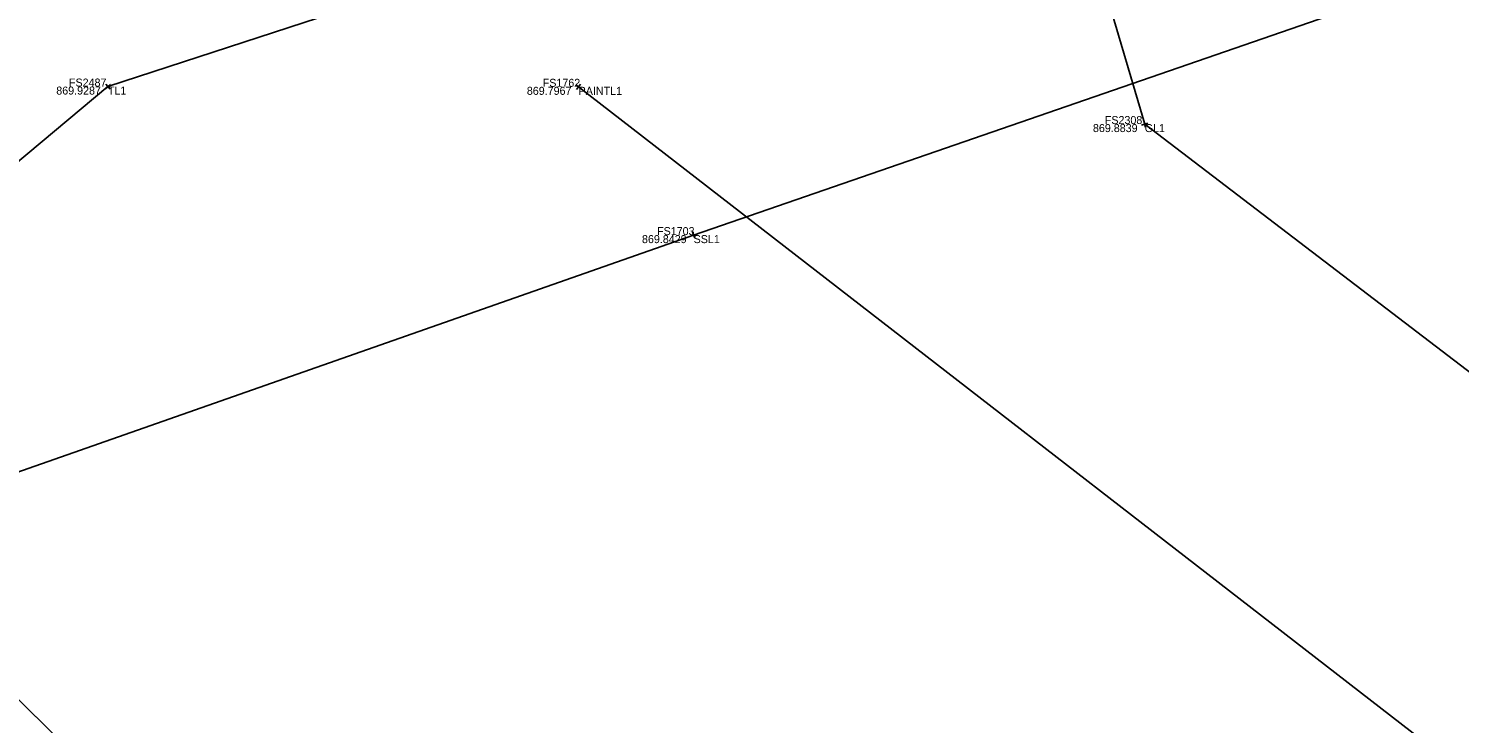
# Model space of a CAD drawing. Extents: x 1479425 to 1480294, y 379351 to 380102.
# Drawn here: x 1479659.17 to 1479669.9, y 379936.02 to 379941.22 of the extents above; entities that cross this region are included whole.
import ezdxf

# ---------------------------------------------------------------- set-up
doc = ezdxf.new("R2010")
doc.units = 0
for name, color, linetype in [('PM_X_Crosswalk', 7, 'Continuous'), ('SV_X_Shot_Marker', 7, 'Continuous'), ('SV_X_Text_Comment', 7, 'Continuous'), ('SV_X_Text_Elevation', 7, 'Continuous'), ('SV_X_Text_Name', 7, 'Continuous'), ('UT_X_Gas', 7, 'Continuous'), ('UT_X_Sanitary_Line', 7, 'Continuous'), ('UT_X_Telecom', 7, 'Continuous'), ('UT_X_Water', 7, 'Continuous')]:
    doc.layers.add(name, color=color, linetype=linetype)

msp = doc.modelspace()

# ---------------------------------------------------------------- linework, layer by layer
at = {"layer": 'PM_X_Crosswalk'}
msp.add_lwpolyline([(1479663.295, 379940.786), (1479694.651, 379916.513)], dxfattribs=at)
at = {"layer": 'SV_X_Shot_Marker'}
for p, q in [((1479659.748, 379940.772), (1479659.786, 379940.804)), ((1479659.751, 379940.807), (1479659.783, 379940.769)), ((1479659.767, 379940.788), (1479659.767, 379940.788)), ((1479663.275, 379940.801), (1479663.315, 379940.771)), ((1479663.31, 379940.806), (1479663.28, 379940.766)), ((1479663.295, 379940.786), (1479663.295, 379940.786)), ((1479667.562, 379940.514), (1479667.514, 379940.5)), ((1479667.531, 379940.531), (1479667.545, 379940.483)), ((1479667.538, 379940.507), (1479667.538, 379940.507)), ((1479664.133, 379939.667), (1479664.181, 379939.683)), ((1479664.149, 379939.699), (1479664.165, 379939.651)), ((1479664.157, 379939.675), (1479664.157, 379939.675))]:
    msp.add_line(p, q, dxfattribs=at)
at = {"layer": 'UT_X_Gas'}
msp.add_lwpolyline([(1479667.444, 379946.572), (1479666.862, 379942.802), (1479667.538, 379940.507), (1479675.403, 379934.504), (1479682.743, 379926.326), (1479692.421, 379916.824), (1479702.659, 379906.694), (1479713.881, 379895.567), (1479724.225, 379885.781), (1479733.117, 379877.795), (1479742.697, 379869.326), (1479754.816, 379857.131), (1479762.869, 379849.318), (1479772.436, 379840.641), (1479780.346, 379832.715), (1479784.901, 379828.191), (1479795.906, 379818.324), (1479806.128, 379806.719), (1479816.671, 379794.927)], dxfattribs=at)
at = {"layer": 'UT_X_Sanitary_Line'}
msp.add_lwpolyline([(1479514.622, 379866.87), (1479542.109, 379880.195), (1479565.169, 379891.725), (1479588.442, 379902.577), (1479600.276, 379909.045), (1479620.421, 379921.063), (1479621.963, 379921.485), (1479624.647, 379923.417), (1479645.234, 379932.512), (1479652.585, 379935.616), (1479664.157, 379939.675), (1479679.103, 379944.837), (1479710.112, 379956.448), (1479736.037, 379968.233), (1479798.147, 379991.168), (1479820.4, 379999.933), (1479823.042, 380000.22)], dxfattribs=at)
at = {"layer": 'UT_X_Telecom'}
msp.add_lwpolyline([(1479654.736, 379936.58), (1479659.767, 379940.788), (1479670.95, 379944.434), (1479693.183, 379956.652)], dxfattribs=at)
at = {"layer": 'UT_X_Water'}
msp.add_lwpolyline([(1479643.418, 379958.357), (1479650.478, 379950.403), (1479653.168, 379946.48), (1479654.757, 379940.471), (1479659.938, 379935.366), (1479675.346, 379920.322), (1479682.752, 379913.809), (1479688.353, 379908.314), (1479695.924, 379900.161), (1479705.441, 379891.596), (1479719.261, 379878.171), (1479726.79, 379870.913), (1479729.608, 379870.544), (1479735.551, 379869.684), (1479739.947, 379866.49), (1479744.65, 379861.847), (1479745.833, 379856.023), (1479753.929, 379847.124), (1479764.701, 379835.97), (1479779.815, 379822.167), (1479798.248, 379804.283), (1479815.468, 379787.444)], dxfattribs=at)

# ---------------------------------------------------------------- texts
at = {"layer": 'SV_X_Text_Comment'}
for s, p in [('TL1', (1479659.767, 379940.728)), ('PAINTL1', (1479663.295, 379940.726)), ('GL1', (1479667.538, 379940.447)), ('SSL1', (1479664.157, 379939.615))]:
    msp.add_text(s, height=0.06, dxfattribs=at).set_placement(p)
at = {"layer": 'SV_X_Text_Elevation'}
for s, p in [('869.9287', (1479659.38, 379940.728)), ('869.7967', (1479662.907, 379940.726)), ('869.8839', (1479667.15, 379940.447)), ('869.8429', (1479663.77, 379939.615))]:
    msp.add_text(s, height=0.06, dxfattribs=at).set_placement(p)
at = {"layer": 'SV_X_Text_Name'}
for s, p in [('FS2487', (1479659.475, 379940.788)), ('FS1762', (1479663.026, 379940.786)), ('FS2308', (1479667.239, 379940.507)), ('FS1703', (1479663.883, 379939.675))]:
    msp.add_text(s, height=0.06, dxfattribs=at).set_placement(p)

doc.saveas('drawing.dxf')
